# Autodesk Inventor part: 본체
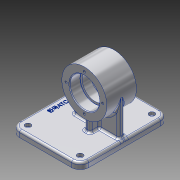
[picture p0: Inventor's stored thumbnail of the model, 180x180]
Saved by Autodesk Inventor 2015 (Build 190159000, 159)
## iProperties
Created: 2019-09
Part Number: 본체
Material: 알루미늄 6061
Document SubType Name: Modeling
Designer: LINEART-SSD.D4.16.07
Density: 2.7 g/cm^3
Appearance: 알루미늄 - 평지
Mass: 554.644 g
Surface Area: 495.891 cm^2
Volume: 205.424 cm^3
Author: LINEART-SSD.D4.16.07
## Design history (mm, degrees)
sketch "스케치1"
  geometry: L1 (49, 63)-(-49, 63); L2 (-49, 63)-(-49, -63); L3 (-49, -63)-(49, -63); L4 (49, -63)-(49, 63); 1 further point
  constraints: 8 end point, 2 parallel, 1 horizontal, 1 perpendicular
  dimensions: "d0" = 126 distance of L3.end L1.start; "d1" = 63 distance from line of L3 point (0, 0); "d2" = 98 distance of L2.end L3.end; "d3" = 49 distance from line of point (0, 0) L4
extrude "돌출1" new body sketch "스케치1" distance "d4" = 9; taper "d5" = 0 deg
sketch "스케치2"
  geometry: L1 (49, 0)-(49, 9) reference; C1 r 32 at (13, 59); 1 further point
  constraints: 1 centre point
  dimensions: "d6" = 32 radius of C1; "d8" = 36 distance from line of L1 C1.centre; "d62" = 59 vertical distance of point (0, 0) C1.centre
extrude "돌출2" join sketch "스케치2" stored distance "d9" = 42; taper "d10" = 0 deg
sketch "스케치3"
  geometry: L1 (-19, 59)-(45, 59); L2 (45, 59)-(45, 0); L3 (45, 0)-(-19, 0); L4 (-19, 0)-(-19, 59); L5 (49, 0)-(-49, 0) reference; L6 (-49, 0)-(-49, 9) reference; L7 (49, 9)-(-49, 9) reference; L8 (49, 0)-(49, 9) reference; C1 r 32 at (13, 59) reference; 3 further points
  constraints: 8 end point, 2 midpoint, 2 parallel, 1 coincident, 1 horizontal, 1 horizontal alignment, 1 perpendicular, 1 vertical alignment
  dimensions: "d11" = 64 distance of L2.end L3.end
extrude "돌출3" join sketch "스케치3" stored distance "d12" = 8; taper "d13" = 0 deg
node "작업 평면1"
sketch "스케치4"
  geometry: L1 (32.408, 17)-(0, 17); L2 (0, 17)-(0, -17); L3 (0, -17)-(32.408, -17); L4 (32.408, -17)-(32.408, 17); 1 further point
  constraints: 8 end point, 2 parallel, 1 horizontal, 1 perpendicular, 1 vertical alignment
  dimensions: "d15" = 17 distance from line of L3 point (0, 0); "d16" = 34 distance of L1.end L2.end; "d17" = 32.40772 distance of L2.end L3.end
extrude "돌출4" join sketch "스케치4" stored distance "d18" = 8; taper "d19" = 0 deg
sketch "스케치5"
  geometry: C1 r 32 at (0, 0) reference; C2 r 21 at (0, 0); 1 further point
  constraints: 1 centre point, 1 coincident
  dimensions: "d20" = 21 radius of C2
extrude "돌출5" cut sketch "스케치5" distance "d21" = 15; taper "d22" = 0 deg
sketch "스케치6"
  geometry: C1 r 21 at (0, 0) reference; C2 r 32 at (0, 0) reference; C3 r 21 at (0, 0); 1 further point
  constraints: 1 centre point, 1 coincident
  dimensions: "d23" = 21 radius of C3
extrude "돌출6" cut sketch "스케치6" distance "d24" = 15; taper "d25" = 0 deg
sketch "스케치7"
  geometry: C1 r 21 at (0, 0) reference; C2 r 32 at (0, 0) reference; C3 r 18 at (0, 0); 1 further point
  constraints: 1 centre point, 1 coincident
  dimensions: "d26" = 18 radius of C3
extrude "돌출7" cut sketch "스케치7" stored distance "d27" = 15; taper "d28" = 0 deg
sketch "스케치8"
  geometry: C1 r 21 at (0, 0) reference; C2 r 32 at (0, 0) reference; 2 further points
  constraints: 1 vertical alignment
  dimensions: "d29" = 26 distance of point (0, 26) C1.centre
hole "구멍1" sketch "스케치8" at (0, 26) diameter "d30" = 3.242; stored, may be unused: countersink angle "d34" = 90 deg, drill point angle "d36" = 118 deg; dims "d31" = 8, "d32" = 4, "d33" = 2, "d35" = 10
sketch "스케치9"
  geometry: L1 (-49, -63)-(49, -63) reference; L2 (-49, 63)-(-49, -63) reference; L3 (49, 63)-(-49, 63) reference; L4 (49, -63)-(49, 63) reference; 5 further points
  constraints: 2 horizontal alignment, 2 vertical alignment
  dimensions: "d40" = 12 distance from line of point (-37, -51) L1; "d41" = 12 distance from line of L2 point (-37, -51); "d42" = 12 distance from line of L4 point (37, -51); "d43" = 12 distance from line of L3 point (37, 51)
hole "구멍2" sketch "스케치9" at (-37, -51), (37, -51), (37, 51), (-37, 51) diameter "d44" = 4.5; stored, may be unused: countersink angle "d48" = 90 deg, drill point angle "d50" = 118 deg; dims "d45" = 8, "d46" = 8, "d47" = 4.4, "d49" = 10
fillet "모깎기1" dims "d51" = 0.3, "d52" = 12, "d53" = 3
fillet "모깎기2" dims "d54" = 3
sketch "스케치10"
  geometry: L1 (-49, 51)-(-49, -51) reference; L2 (37, 63)-(-37, 63) reference; 2 further points
  constraints: 1 other
  dimensions: "d55" = 10 distance from line of point (-39, 0) L1; "d56" = 63 distance from line of point (-39, 0) L2
feature "엠보싱1" sketch "스케치10" dims "d0" = 126, "d1" = 63, "d2" = 98, "d3" = 49, "d57" = 0.5, "d58" = 0
chamfer "모따기1" distance "d59" = 1; stored, may be unused: second distance "d60" = 2, angle "d61" = 45 deg
node "솔리드1"
pattern_circular "원형 패턴1" dims angle "d38" = 360 deg
mirror "대칭1"
node "투영된 루프1"
node "투영된 루프2"
node "투영된 루프3"
node "투영된 루프4"
node "투영된 루프5"
node "투영된 루프6"
node "투영된 루프7"
other parameters: "d14" = 13
